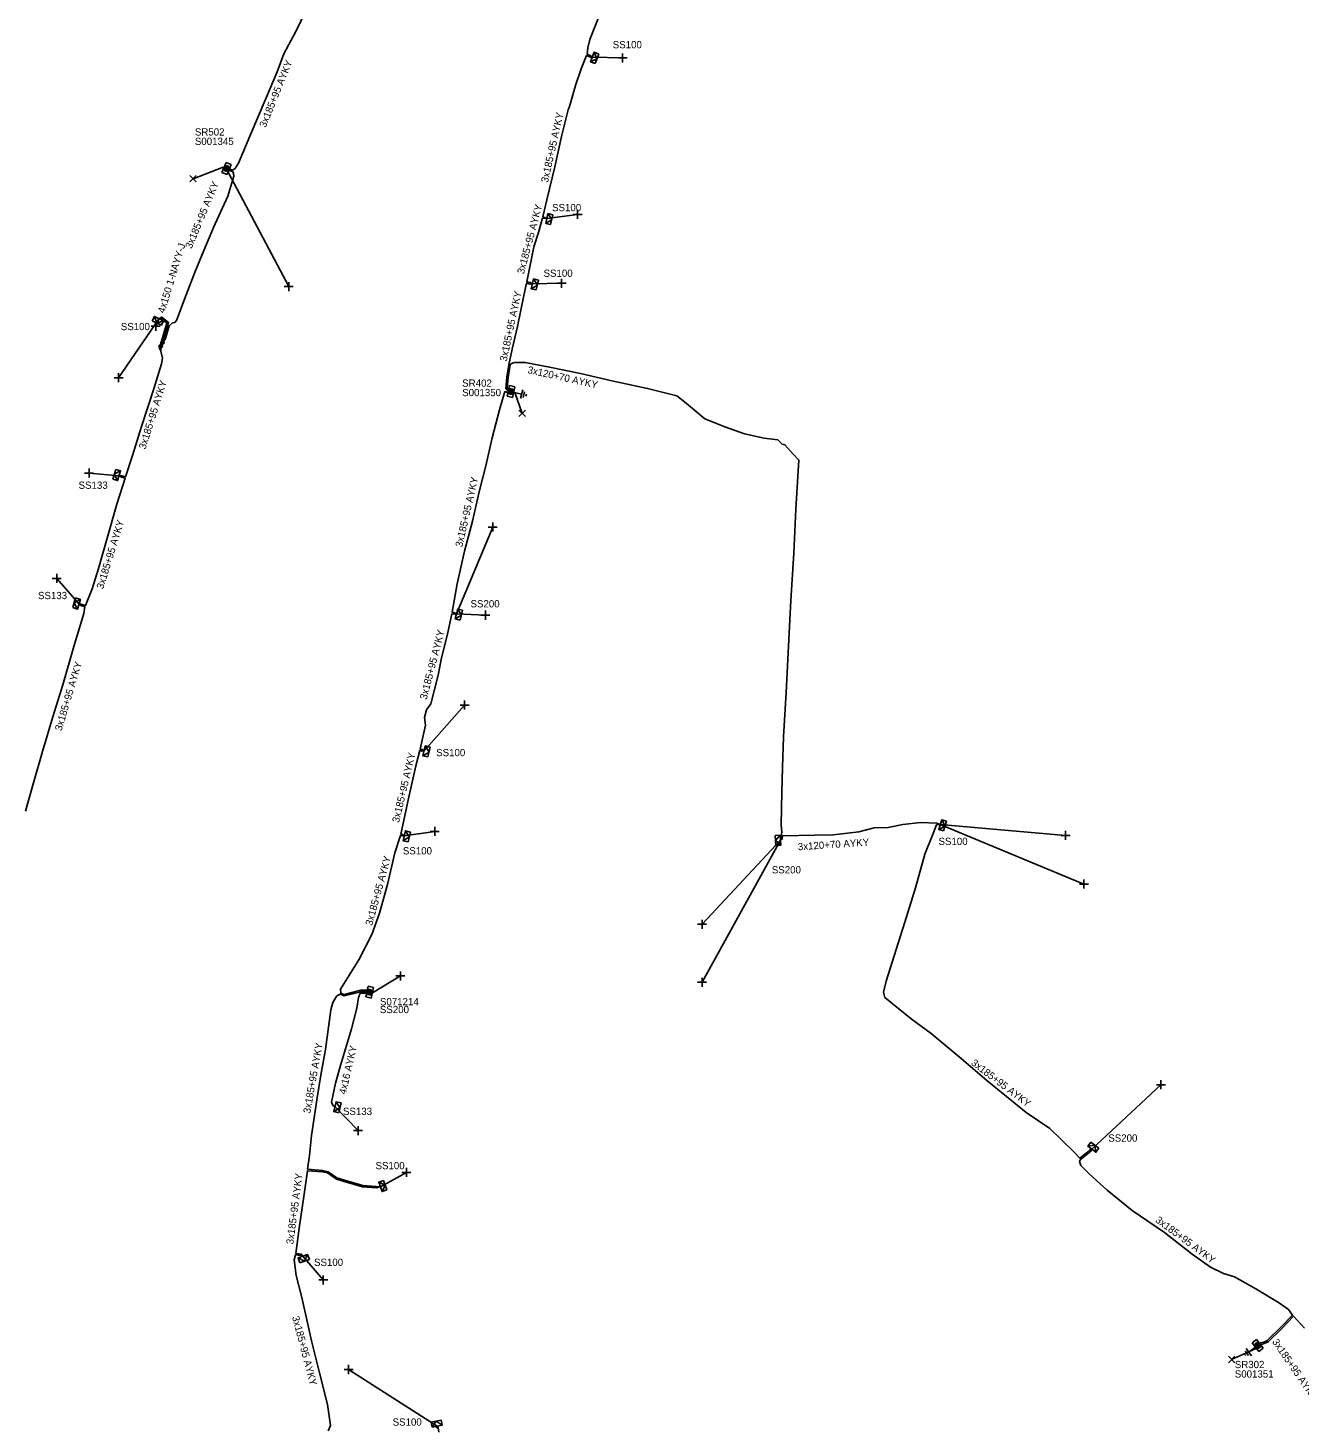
# Model space of a CAD drawing. Extents: x -763093 to -760976, y -1155572 to -1152009.
# Drawn here: x -762125.9 to -761950.7, y -1155234.4 to -1155041.4 of the extents above; entities that cross this region are included whole.
import ezdxf

# ---------------------------------------------------------------- set-up
doc = ezdxf.new("R2010")
doc.units = 0
for name, color, linetype in [('Vrstva 1', 7, 'Continuous'), ('Vrstva 14', 7, 'Continuous'), ('Vrstva 15', 7, 'Continuous'), ('Vrstva 19', 7, 'Continuous'), ('Vrstva 28', 7, 'Continuous'), ('Vrstva 29', 7, 'Continuous'), ('Vrstva 30', 7, 'Continuous'), ('Vrstva 31', 7, 'Continuous'), ('Vrstva 33', 7, 'Continuous'), ('Vrstva 34', 7, 'Continuous'), ('Vrstva 4', 7, 'Continuous'), ('Vrstva 5', 7, 'Continuous'), ('Vrstva 59', 7, 'Continuous'), ('Vrstva 6', 7, 'Continuous'), ('Vrstva 8', 7, 'Continuous'), ('Vrstva 9', 7, 'Continuous')]:
    doc.layers.add(name, color=color, linetype=linetype)

# ---------------------------------------------------------------- blocks, each defined once
blk = doc.blocks.new('NN870')
at = {"layer": 'Vrstva 4'}
for points in [[(0, -0.25), (0.5, 0), (0, 0.25), (-0.5, 0), (0, -0.25)], [(0.37, 0), (0, 0.19), (-0.36, 0), (0, -0.19), (0.37, 0)], [(0.24, 0), (0, 0.12), (-0.25, 0), (0, -0.12), (0.24, 0)], [(0.12, 0), (0, 0.06), (-0.13, 0), (0, -0.06), (0.12, 0)]]:
    blk.add_lwpolyline(points, dxfattribs=at)
blk = doc.blocks.new('NN800')
at = {"layer": 'Vrstva 1'}
for points in [[(-0.44, 0.44), (0.44, -0.44)], [(-0.44, -0.44), (0.44, 0.44)]]:
    blk.add_lwpolyline(points, dxfattribs=at)
blk = doc.blocks.new('NN620')
at = {"layer": 'Vrstva 8'}
for points in [[(0.75, 0), (-0.75, 0)], [(-0.75, 0), (-0.75, -0.75)], [(0.75, -0.75), (0.75, 0)], [(-0.75, -0.75), (0.75, -0.75)], [(0.37, -0.18), (-0.38, -0.18)], [(-0.38, -0.18), (-0.38, -0.56)], [(-0.38, -0.56), (0.37, -0.56)], [(0.32, -0.23), (-0.33, -0.23)], [(-0.33, -0.23), (-0.33, -0.51)], [(-0.33, -0.51), (0.32, -0.51)], [(0.27, -0.27), (-0.28, -0.27)], [(-0.28, -0.27), (-0.28, -0.46)], [(-0.28, -0.46), (0.27, -0.46)], [(0.23, -0.32), (-0.23, -0.32)], [(-0.23, -0.32), (-0.23, -0.42)], [(-0.23, -0.42), (0.23, -0.42)], [(-0.19, -0.37), (0.19, -0.37)], [(0.23, -0.42), (0.23, -0.32)], [(0.27, -0.46), (0.27, -0.27)], [(0.32, -0.51), (0.32, -0.23)], [(0.37, -0.56), (0.37, -0.18)]]:
    blk.add_lwpolyline(points, dxfattribs=at)
blk = doc.blocks.new('NN630')
at = {"layer": 'Vrstva 9'}
for points in [[(0, -0.7), (-0.7, 0)], [(-0.7, -0.7), (-0.7, 0), (0.7, 0), (0.7, -0.7)], [(-0.7, -0.7), (0.7, -0.7)], [(0, -0.7), (0.7, 0)]]:
    blk.add_lwpolyline(points, dxfattribs=at)
blk = doc.blocks.new('NN810')
at = {"layer": 'Vrstva 14'}
for points in [[(0.63, -1.89), (-0.62, -1.89)], [(0, -0.64), (0, -1.89)], [(0.39, -2.2), (-0.4, -2.2)], [(0, -2.52), (-0.12, -2.52)], [(0.14, -2.52), (0, -2.52)]]:
    blk.add_lwpolyline(points, dxfattribs=at)

msp = doc.modelspace()

# ---------------------------------------------------------------- linework, layer by layer
at = {"layer": 'Vrstva 5'}
for points in [[(-762087.03, -1155037.83), (-762088.98, -1155041.85), (-762090.66, -1155044.99), (-762091.58, -1155047.51), (-762093.11, -1155051.07), (-762095.34, -1155056.35), (-762096.9, -1155060.07), (-762097.39, -1155060.8), (-762097.76, -1155061.03), (-762098.11, -1155060.9)], [(-762059.79, -1155091.48), (-762060.08, -1155091.17), (-762059.92, -1155089.6), (-762059.67, -1155087.87), (-762059.21, -1155085.7), (-762058.46, -1155082.58), (-762057.56, -1155078.33), (-762057.21, -1155076.62), (-762056.7, -1155076.76), (-762056.4, -1155076.72), (-762056.66, -1155076.55), (-762057.17, -1155076.42), (-762056.2, -1155071.63), (-762055.57, -1155069.63), (-762054.99, -1155067.68), (-762054.41, -1155067.71), (-762054.94, -1155067.48), (-762054.39, -1155065.13), (-762053.3, -1155060.59), (-762052.37, -1155056.4), (-762051.48, -1155052.72), (-762051.28, -1155052.28), (-762050.44, -1155049.36), (-762049.66, -1155047.06), (-762048.93, -1155045.24), (-762048.39, -1155045.45), (-762048.15, -1155045.45), (-762048.33, -1155045.27), (-762048.87, -1155045.04), (-762048.74, -1155044.18), (-762048.47, -1155043.02), (-762046.66, -1155038.38)], [(-762098.17, -1155061.07), (-762097.77, -1155061.24), (-762097.62, -1155061.47), (-762097.56, -1155061.88), (-762098.41, -1155064.64), (-762100.35, -1155068.94), (-762101.93, -1155072.69), (-762102.91, -1155075.03), (-762104.16, -1155078.21), (-762105.47, -1155081.78), (-762105.71, -1155082.05), (-762106.03, -1155082.11), (-762106.49, -1155082.51), (-762107, -1155084.23), (-762107.39, -1155084.83)], [(-762107.65, -1155085.32), (-762107.69, -1155085.07), (-762106.8, -1155082.14), (-762107.53, -1155081.51), (-762107.88, -1155081.5), (-762107.51, -1155081.29), (-762106.56, -1155082.06), (-762107.35, -1155084.62), (-762107.39, -1155084.83)], [(-762107.65, -1155085.32), (-762107.61, -1155086), (-762107.4, -1155086.98), (-762107.54, -1155087.73), (-762108.59, -1155091.2), (-762110.28, -1155096.36), (-762111.54, -1155100.36), (-762112.49, -1155103.31), (-762113.02, -1155103.17), (-762113.38, -1155103.17), (-762113.05, -1155103.37), (-762112.55, -1155103.51), (-762113.69, -1155107.07), (-762115.13, -1155112.1), (-762116.24, -1155115.94), (-762117.11, -1155118.76), (-762118.03, -1155121.04), (-762118.6, -1155120.88), (-762118.91, -1155120.88), (-762118.65, -1155121.06), (-762118.09, -1155121.23), (-762118.26, -1155122.14), (-762119.61, -1155126.69), (-762121.15, -1155132.01), (-762122.5, -1155136.42), (-762123.94, -1155141.19), (-762125.19, -1155145.52), (-762126.31, -1155149.4)], [(-762059.73, -1155091.26), (-762059.88, -1155091.11), (-762059.72, -1155089.62), (-762059.46, -1155087.82), (-762059.16, -1155087.66), (-762058.83, -1155087.58), (-762057.4, -1155087.55), (-762054.04, -1155088.18), (-762049.77, -1155089.08), (-762045.46, -1155090.08), (-762040.53, -1155091.14), (-762036.47, -1155092.15), (-762035.44, -1155093), (-762032.64, -1155095.34), (-762029.86, -1155096.44), (-762027.14, -1155097.4), (-762024.44, -1155097.97), (-762022.57, -1155098.22), (-762021.98, -1155098.81), (-762021.59, -1155098.9), (-762020.47, -1155100.21), (-762019.66, -1155101.02), (-762020.07, -1155107.76), (-762020.34, -1155113.85), (-762020.76, -1155120.35), (-762021.09, -1155126.67), (-762021.39, -1155133.05), (-762021.77, -1155139.18), (-762021.92, -1155143.39), (-762022.03, -1155146.77), (-762022.08, -1155151.29), (-762022.02, -1155152.32), (-762022.2, -1155153.42), (-762021.96, -1155153.24), (-762021.9, -1155152.79), (-762017.48, -1155152.74), (-762014.9, -1155152.67), (-762011.4, -1155152.27), (-762009.3, -1155151.72), (-762007.37, -1155151.66), (-762005.32, -1155151.27), (-762002.89, -1155150.96), (-762000.63, -1155151.08), (-762000.17, -1155151.26)], [(-762079.21, -1155174.07), (-762080.07, -1155174.1), (-762082.35, -1155174.67), (-762082.79, -1155174.49), (-762082.86, -1155173.93), (-762080.35, -1155169.89), (-762078.54, -1155166.39), (-762077.48, -1155163.48), (-762076.38, -1155159.51), (-762075.39, -1155155.14), (-762074.57, -1155152.75), (-762074.33, -1155152.83), (-762074.06, -1155152.8), (-762074.28, -1155152.63), (-762074.52, -1155152.56), (-762073.5, -1155147.67), (-762072.48, -1155143.16), (-762071.93, -1155141.05), (-762071.64, -1155141.12), (-762071.33, -1155141.1), (-762071.59, -1155140.93), (-762071.88, -1155140.85), (-762071.16, -1155137.56), (-762071.28, -1155136.5), (-762071.02, -1155135.44), (-762070.42, -1155134.63), (-762069.4, -1155130.67), (-762068.93, -1155128.27), (-762068.12, -1155125.01), (-762067.5, -1155122.19), (-762067.2, -1155122.25), (-762066.87, -1155122.22), (-762067.16, -1155122.06), (-762067.46, -1155121.99), (-762066.76, -1155118.07), (-762065.74, -1155113.55), (-762064.68, -1155109.42), (-762063.73, -1155105.38), (-762062.81, -1155101.8), (-762061.95, -1155097.92), (-762060.92, -1155094.1), (-762060.2, -1155091.57), (-762059.83, -1155091.69)], [(-761956.04, -1155222.72), (-761955.56, -1155222.61), (-761955.09, -1155222.4), (-761953.18, -1155220.52), (-761951.61, -1155218.87), (-761952.16, -1155218.09), (-761953.53, -1155217.12), (-761956.64, -1155215.26), (-761959.59, -1155213.6), (-761961.13, -1155213.15), (-761962.91, -1155212.25), (-761965.43, -1155210.46), (-761969.25, -1155207.49), (-761973.73, -1155204.47), (-761977.14, -1155201.67), (-761979.63, -1155199.39), (-761980.77, -1155198.27), (-761980.96, -1155197.72), (-761980.9, -1155197.49), (-761979.36, -1155196.23), (-761979.27, -1155196), (-761979.53, -1155196.08), (-761979.99, -1155196.53), (-761980.92, -1155197.25), (-761981.75, -1155196.39), (-761985.08, -1155193.17), (-761988.3, -1155190.95), (-761993.74, -1155186.53), (-761997.29, -1155183.5), (-762001.43, -1155180.07), (-762004.17, -1155178.06), (-762007.83, -1155175.08), (-762008, -1155174.37), (-762007.61, -1155172.83), (-762006.26, -1155168.47), (-762005.06, -1155164.71), (-762003.56, -1155159.96), (-762002.3, -1155155.36), (-762001.15, -1155152.48), (-762000.67, -1155151.28), (-762000.17, -1155151.26)], [(-762084.55, -1155234.83), (-762084.22, -1155234.08), (-762084.65, -1155231.22), (-762085.74, -1155226.85), (-762086.87, -1155222.44), (-762087.43, -1155219.95), (-762088.18, -1155216.45), (-762088.96, -1155213.42), (-762089.24, -1155211.24), (-762089.04, -1155210.59), (-762088.34, -1155210.67), (-762088.05, -1155210.77), (-762088.26, -1155210.47), (-762089, -1155210.39), (-762088.52, -1155206.59), (-762087.98, -1155202.83), (-762087.41, -1155198.97), (-762085.36, -1155199.13), (-762084.66, -1155199.29), (-762083.43, -1155200.13), (-762082.35, -1155200.46), (-762079.81, -1155201.2), (-762077.89, -1155201.35), (-762077.36, -1155201.2), (-762079.77, -1155201), (-762082.29, -1155200.26), (-762083.35, -1155199.95), (-762084.58, -1155199.11), (-762085.32, -1155198.93), (-762087.4, -1155198.76), (-762087.12, -1155196.9), (-762086.87, -1155194.11), (-762086.08, -1155188.92), (-762085.58, -1155185.79), (-762084.92, -1155182.25), (-762084.2, -1155176.81), (-762083.92, -1155175.77), (-762083.36, -1155174.87), (-762082.9, -1155174.66), (-762082.37, -1155174.87), (-762080.06, -1155174.3), (-762079.31, -1155174.27)], [(-762079.35, -1155174.48), (-762080.14, -1155174.5), (-762080.37, -1155175.1), (-762080.6, -1155176.55), (-762081.32, -1155179.4), (-762082.87, -1155184.46), (-762083.54, -1155186.9), (-762084.1, -1155189.54), (-762083.87, -1155190.01), (-762083.62, -1155190.14)], [(-761949.95, -1155220.67), (-761951.48, -1155219.02), (-761953.04, -1155220.66), (-761954.97, -1155222.56), (-761955.5, -1155222.79), (-761955.94, -1155222.91)], [(-762069.32, -1155235), (-762069.4, -1155234.42), (-762069.52, -1155234.17), (-762069.6, -1155234.45)]]:
    msp.add_lwpolyline(points, dxfattribs=at)
at = {"layer": 'Vrstva 59'}
for points in [[(-762048.15, -1155045.45), (-762043.96, -1155045.58)], [(-762099.03, -1155060.62), (-762103.18, -1155062.22)], [(-762098.28, -1155061.39), (-762089.99, -1155077.1)], [(-762054.41, -1155067.71), (-762050.18, -1155067.14)], [(-762056.4, -1155076.72), (-762052.37, -1155076.63)], [(-762107.88, -1155081.5), (-762113.46, -1155089.66)], [(-762107.88, -1155081.5), (-762108.33, -1155082.56)], [(-762058.84, -1155091.69), (-762057.81, -1155094.57)], [(-762113.38, -1155103.17), (-762117.53, -1155102.8)], [(-762066.87, -1155122.22), (-762061.86, -1155110.24)], [(-762118.91, -1155120.88), (-762121.98, -1155117.33)], [(-762066.87, -1155122.22), (-762062.88, -1155122.39)], [(-762071.33, -1155141.1), (-762065.75, -1155134.79)], [(-762074.06, -1155152.8), (-762069.87, -1155152.19)], [(-762000.17, -1155151.26), (-761980.36, -1155159.47)], [(-762000.17, -1155151.26), (-761982.88, -1155152.75)], [(-762022.2, -1155153.42), (-762033, -1155173)], [(-762022.2, -1155153.42), (-762033, -1155165)], [(-762078.45, -1155174.45), (-762074.6, -1155172.11)], [(-761979.27, -1155196), (-761969.75, -1155187.13)], [(-762083.62, -1155190.14), (-762080.43, -1155193.44)], [(-762077.36, -1155201.2), (-762073.77, -1155199.2)], [(-762088.05, -1155210.77), (-762085.24, -1155214.02)], [(-761956.7, -1155223.52), (-761960, -1155225)], [(-762069.52, -1155234.17), (-762081.75, -1155226.38)]]:
    msp.add_lwpolyline(points, dxfattribs=at)

# ---------------------------------------------------------------- block references
at = {"layer": 'Vrstva 15'}
for p, rotation in [((-762059.72, -1155091.48), 76.61486266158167), ((-761956.11, -1155222.85), -53.5734138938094)]:
    msp.add_blockref('NN810', p, dxfattribs=dict(at, rotation=rotation))
at = {"layer": 'Vrstva 19'}
for p, rotation in [((-762107.65, -1155085.32), 74.84593330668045), ((-762107.39, -1155084.83), 72.95606665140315)]:
    msp.add_blockref('NN870', p, dxfattribs=dict(at, rotation=rotation))
at = {"layer": 'Vrstva 28'}
for p, rotation in [((-762098.22, -1155060.96), -112.15513642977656), ((-762059.72, -1155091.48), 76.69698103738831), ((-762079.2, -1155174.27), 76.57934998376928), ((-761956.11, -1155222.85), -52.94347218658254)]:
    msp.add_blockref('NN620', p, dxfattribs=dict(at, rotation=rotation))
at = {"layer": 'Vrstva 31'}
for p, rotation in [((-762048.15, -1155045.45), 68.90428335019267), ((-762054.41, -1155067.71), 77.14114164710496), ((-762056.4, -1155076.72), 76.87594447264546), ((-762107.88, -1155081.5), -25.259799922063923), ((-762113.38, -1155103.17), -107.36438054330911), ((-762118.91, -1155120.88), -106.9478527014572), ((-762066.87, -1155122.22), 76.26601954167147), ((-762071.33, -1155141.1), 76.84668609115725), ((-762000.17, -1155151.26), 72.98762776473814), ((-762074.06, -1155152.8), 76.41703612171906), ((-762022.2, -1155153.42), -86.59374406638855), ((-762083.62, -1155190.14), 76.5651805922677), ((-761979.27, -1155196), 143.13699167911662), ((-762077.36, -1155201.2), 109.06802496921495), ((-762088.05, -1155210.77), 19.674641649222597), ((-762069.52, -1155234.17), -168.76244728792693)]:
    msp.add_blockref('NN630', p, dxfattribs=dict(at, rotation=rotation))
at = {"layer": 'Vrstva 34'}
for p, rotation in [((-762043.96, -1155045.58), 45), ((-762050.18, -1155067.15), 45), ((-762089.99, -1155077.1), 45), ((-762052.37, -1155076.64), 45), ((-762108.33, -1155082.56), 45), ((-762113.46, -1155089.66), 45), ((-762117.53, -1155102.8), 45), ((-762061.86, -1155110.24), 45.00000009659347), ((-762121.98, -1155117.33), 45), ((-762062.88, -1155122.39), 45), ((-762065.75, -1155134.79), 44.99999995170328), ((-762069.87, -1155152.19), 45), ((-761982.88, -1155152.75), 45), ((-761980.36, -1155159.47), 44.99999995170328), ((-762033, -1155165), 45), ((-762074.6, -1155172.12), 45), ((-762033, -1155173), 45), ((-761969.75, -1155187.13), 45), ((-762080.43, -1155193.44), 45), ((-762073.77, -1155199.2), 45), ((-762085.24, -1155214.02), 45.00000009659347), ((-762081.75, -1155226.38), 45)]:
    msp.add_blockref('NN800', p, dxfattribs=dict(at, rotation=rotation))
for p in [(-762103.18, -1155062.22), (-762057.81, -1155094.57), (-761960, -1155225)]:
    msp.add_blockref('NN800', p, dxfattribs=at)

# ---------------------------------------------------------------- texts
at = {"layer": 'Vrstva 29'}
for s, p in [('S001345', (-762102.94, -1155057.57)), ('S001350', (-762066.08, -1155092.2)), ('S071214', (-762077.42, -1155176.17)), ('S001351', (-761959.56, -1155227.49))]:
    msp.add_text(s, height=1, dxfattribs=at).set_placement(p)
at = {"layer": 'Vrstva 30'}
for s, p in [('SR502', (-762102.94, -1155056.27)), ('SR402', (-762066.08, -1155090.9)), ('SS200', (-762077.43, -1155177.25)), ('SR302', (-761959.56, -1155226.19))]:
    msp.add_text(s, height=1, dxfattribs=at).set_placement(p)
at = {"layer": 'Vrstva 33'}
for s, p in [('SS100', (-762045.32, -1155044.24)), ('SS100', (-762053.69, -1155066.7)), ('SS100', (-762054.86, -1155075.75)), ('SS100', (-762113.15, -1155083.1)), ('SS133', (-762118.97, -1155104.97)), ('SS133', (-762124.57, -1155120.18)), ('SS200', (-762064.93, -1155121.32)), ('SS100', (-762069.67, -1155141.83)), ('SS100', (-762074.26, -1155155.37)), ('SS100', (-762000.41, -1155154.07)), ('SS200', (-762023.39, -1155157.99)), ('SS133', (-762082.52, -1155191.29)), ('SS200', (-761977, -1155194.97)), ('SS100', (-762078.03, -1155198.77)), ('SS100', (-762086.51, -1155212.1)), ('SS100', (-762075.67, -1155234.12))]:
    msp.add_text(s, height=1, dxfattribs=at).set_placement(p)
at = {"layer": 'Vrstva 6'}
for s, rotation, p in [('3x185+95 AYKY', 67.82, (-762093.18, -1155055.25)), ('3x185+95 AYKY', 77.336, (-762054.26, -1155062.83)), ('3x185+95 AYKY', 67.339, (-762103.4, -1155071.96)), ('3x185+95 AYKY', 75.045, (-762057.57, -1155075.43)), ('4x150 1-NAYY-J', 73.002, (-762107.14, -1155080.83)), ('3x185+95 AYKY', 77.964, (-762059.95, -1155087.48)), ('3x120+70 AYKY', 347.423, (-762057.13, -1155089.01)), ('3x185+95 AYKY', 72.493, (-762109.75, -1155099.59)), ('3x185+95 AYKY', 76.982, (-762066.08, -1155113.07)), ('3x185+95 AYKY', 72.906, (-762115.58, -1155118.87)), ('3x185+95 AYKY', 75.445, (-762070.98, -1155134.1)), ('3x185+95 AYKY', 73.279, (-762121.32, -1155138.41)), ('3x185+95 AYKY', 76.646, (-762074.79, -1155151.06)), ('3x120+70 AYKY', 3.734, (-762019.77, -1155154.81)), ('3x185+95 AYKY', 74.638, (-762078.5, -1155165.26)), ('3x185+95 AYKY', 79.906, (-762087.03, -1155191.13)), ('4x16 AYKY', 76.772, (-762082.14, -1155188.52)), ('3x185+95 AYKY', 322.76, (-761996.01, -1155184.3)), ('3x185+95 AYKY', 82.48, (-762089.37, -1155209.17)), ('3x185+95 AYKY', 323.36, (-761970.6, -1155205.96)), ('3x185+95 AYKY', 284.819, (-762089.55, -1155219.14)), ('3x185+95 AYKY', 304.359, (-761954.46, -1155222.56))]:
    msp.add_text(s, height=1, rotation=rotation, dxfattribs=at).set_placement(p)

doc.saveas('drawing.dxf')
